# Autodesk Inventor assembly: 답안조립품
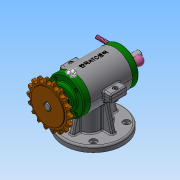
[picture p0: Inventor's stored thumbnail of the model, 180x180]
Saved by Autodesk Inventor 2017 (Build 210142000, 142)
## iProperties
Part Number: 답안조립품
Material: 일반
Document SubType Name: Assembly
Designer: user
Mass: 1211.37 g
Surface Area: 1369.29 cm^2
Volume: 434.957 cm^3
Density: 2.78504 g/cm^3
Author: user
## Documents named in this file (19)
- C:\Users\user\Desktop\611206V1003\답안조립품.iam
- C:\Users\user\Desktop\611206V1003\본체.ipt
- C:\Users\user\Desktop\611206V1003\상부커버.ipt
- C:\Users\user\Desktop\611206V1003\볼트 M4 x 16.ipt
- C:\Users\user\Desktop\611206V1003\앞커버.ipt
- C:\Users\user\Desktop\611206V1003\뒤커버.ipt
- C:\Users\user\Desktop\611206V1003\베어링 6201.ipt
- C:\Users\user\Desktop\611206V1003\베어링 6202.ipt
- C:\Users\user\Desktop\611206V1003\편심축.ipt
- C:\Users\user\Desktop\611206V1003\오일실 12 x 22 x 7.ipt
- C:\Users\user\Desktop\611206V1003\키 4 x 4.ipt
- C:\Users\user\Desktop\611206V1003\볼트 M3 x 0.5.ipt
- C:\Users\user\Desktop\611206V1003\스프로킷.ipt
- C:\Users\user\Desktop\611206V1003\멈춤나사 M3.ipt
- C:\Users\user\Desktop\611206V1003\레버.ipt
- C:\Users\user\Desktop\611206V1003\와셔.ipt
- C:\Users\user\Desktop\611206V1003\너트 M4.ipt
- C:\Users\user\Desktop\611206V1003\슬라이드.ipt
- C:\Users\user\Desktop\611206V1003\가변스프링.ipt
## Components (7 placed, 4 different names)
1. ISO 4762 M4 x 16:1
2. ISO 4762 M4 x 16:2
3. ISO 7091 ST 4 - 100 HV:1
4. ISO 7091 ST 4 - 100 HV:2
5. ISO 4032 M4:1
6. ISO 4032 M4:2
7. 가변스프링:1
